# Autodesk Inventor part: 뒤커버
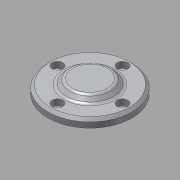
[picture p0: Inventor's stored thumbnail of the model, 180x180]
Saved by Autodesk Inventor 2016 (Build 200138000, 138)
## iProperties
Created: 2015-09
Part Number: 뒤커버
Material: 알루미늄 6061
Document SubType Name: Modeling
Designer: mduedu
Density: 1 g/cm^3
Appearance: 알루미늄 - 평지
Author: mduedu
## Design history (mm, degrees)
sketch "스케치1"
  geometry: L1 (0, 7.5)-(0, -7.5); L2 (0, 7.5)-(14, 7.5); L3 (14, 7.5)-(18, 3.5); L4 (18, 3.5)-(31, 3.5); L5 (31, 3.5)-(31, -2.5); L6 (31, -2.5)-(17.5, -2.5); L7 (17.5, -2.5)-(17.5, -7.5); L8 (17.5, -7.5)-(0, -7.5); 2 further points
  constraints: 16 end point, 3 parallel, 2 perpendicular, 1 coincident, 1 horizontal, 1 midpoint, 1 vertical
  dimensions: "d0" = 15 distance of L1.start L1.end; "d1" = 4 distance between parallel lines of L4 L2; "d2" = 6 distance of L4.end L5.end; "d3" = 36 diameter of L3.end L1; "d4" = 35 diameter of L7 L1; "d5" = 62 diameter of L5 L1; "d7" = 45 deg angle of L3 L5
revolve "회전1" sketch "스케치1" stored, may be unused: angle "d8" = 90 deg
hole "구멍1" diameter "d11" = 24; stored, may be unused: countersink angle "d15" = 90 deg, drill point angle "d17" = 0 deg; dims "d9" = 10, "d10" = 10, "d12" = 6, "d13" = 4, "d14" = 2, "d16" = 8
fillet "모깎기1" dims "d18" = 3
chamfer "모따기1" distance "d19" = 1; stored, may be unused: second distance "d20" = 2, angle "d21" = 45 deg
chamfer "모따기2" distance "d22" = 2; stored, may be unused: second distance "d23" = 2, angle "d24" = 45 deg
fillet "모깎기2" dims "d25" = 3
fillet "모깎기3" dims "d26" = 3
sketch "스케치2" dims "d27" = 48
  geometry: 6 further points
  constraints: 2 vertical alignment, 1 coincident, 7 other
  dimensions: "d33" = 360 deg dimension on point (0, 0) point (0, 24) (derived)
sketch "스케치3"
  geometry: 4 further points
hole "구멍2" sketch "스케치3" at (-24, 0), (0, -24), (24, 0), (0, 24) diameter "d35" = 4.5; stored, may be unused: countersink angle "d39" = 90 deg, drill point angle "d41" = 0 deg; dims "d36" = 6, "d37" = 8, "d38" = 4.6, "d40" = 8
node "솔리드1"
